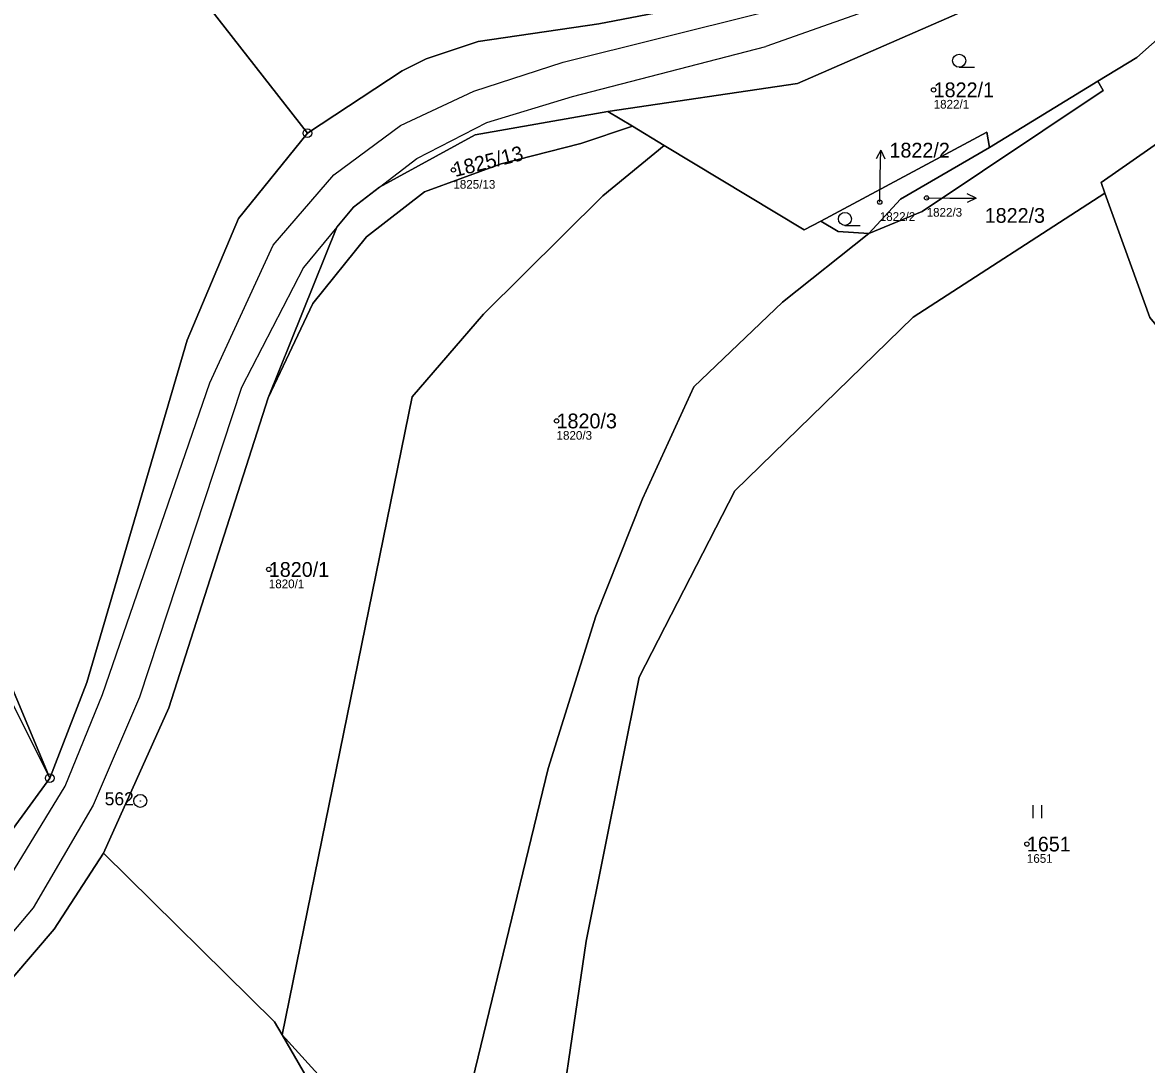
# Model space of a CAD drawing. Extents: x -762274 to -759271, y -1061928 to -1059060.
# Drawn here: x -761021.1 to -760891.6, y -1060368.9 to -1060248.8 of the extents above; entities that cross this region are included whole.
import ezdxf

# ---------------------------------------------------------------- set-up
doc = ezdxf.new("R2010")
doc.units = 0
for name, color, linetype in [('Definiční body', 7, 'Continuous'), ('Hranice parcel', 7, 'Continuous'), ('Parcelní čísla', 7, 'Continuous'), ('Polygon parcely', 7, 'Continuous'), ('Pop  PČ popisy', 7, 'Continuous'), ('Vnitřní kresba', 7, 'Continuous'), ('Značky bodu BP', 7, 'Continuous'), ('Značky kultur', 7, 'Continuous')]:
    doc.layers.add(name, color=color, linetype=linetype)

msp = doc.modelspace()

# ---------------------------------------------------------------- linework, layer by layer
at = {"layer": 'Definiční body'}
for centre in [(-760916.13, -1060256.56), (-760971.48, -1060265.79), (-760922.34, -1060269.5), (-760916.94, -1060269.01), (-760959.59, -1060294.71), (-760992.75, -1060311.82), (-760905.39, -1060343.46)]:
    msp.add_circle(centre, 0.25, dxfattribs=at)
at = {"layer": 'Hranice parcel'}
for p, q in [((-760909.68, -1060263.19), (-760897.21, -1060255.57)), ((-760953.67, -1060259.06), (-760950.85, -1060260.75)), ((-760950.85, -1060260.75), (-760947.17, -1060262.97)), ((-760974.43, -1060394.46), (-760991.21, -1060365.45))]:
    msp.add_line(p, q, dxfattribs=at)
for points in [[(-761078.48, -1060213.62), (-761057.56, -1060250.11), (-761042.29, -1060277.77), (-761018, -1060335.87)], [(-760988.31, -1060261.56), (-760977.4, -1060254.36), (-760974.6, -1060253), (-760968.64, -1060250.99), (-760954.7, -1060248.96), (-760947.29, -1060247.52), (-760940.52, -1060246.19), (-760931.32, -1060243.79), (-760922.41, -1060240.54), (-760918.23, -1060238.58), (-760916.79, -1060234.33)], [(-761006.62, -1060234.74), (-761002.03, -1060243.92), (-760988.31, -1060261.56)], [(-760897.21, -1060255.57), (-760892.72, -1060252.83), (-760874.41, -1060236.6)], [(-760904.18, -1060243.78), (-760912.52, -1060247.42), (-760931.82, -1060255.83), (-760953.67, -1060259.06)], [(-760874.93, -1060249.88), (-760883.71, -1060258.09), (-760896.84, -1060267.23), (-760896.39, -1060268.47)], [(-761018, -1060335.87), (-761037.77, -1060296.38), (-761044.15, -1060282.19), (-761061.78, -1060253.34)], [(-760897.21, -1060255.57), (-760896.58, -1060256.63), (-760917.46, -1060270.59), (-760923.61, -1060273.11)], [(-760992.81, -1060292.05), (-760984.91, -1060272.38), (-760983, -1060270.07), (-760980, -1060267.77), (-760968.98, -1060261.75), (-760953.67, -1060259.06)], [(-760988.31, -1060261.56), (-760996.24, -1060271.37), (-761002.17, -1060285.41), (-761013.73, -1060324.84), (-761018, -1060335.87)], [(-760950.85, -1060260.75), (-760956.8, -1060262.74), (-760965.96, -1060265.09), (-760974.8, -1060268.32), (-760981.51, -1060273.48), (-760987.67, -1060281.19), (-760992.81, -1060292.05)], [(-760929.15, -1060271.68), (-760909.99, -1060261.44), (-760909.68, -1060263.19)], [(-760991.21, -1060365.45), (-760976.24, -1060291.93), (-760967.99, -1060282.4), (-760954.26, -1060268.77), (-760947.17, -1060262.97)], [(-760947.17, -1060262.97), (-760931.05, -1060272.69), (-760929.15, -1060271.68)], [(-760923.61, -1060273.11), (-760919.95, -1060269.16), (-760909.68, -1060263.19)], [(-760896.39, -1060268.47), (-760918.5, -1060282.74), (-760939.03, -1060302.75), (-760950.07, -1060324.21), (-760956.19, -1060354.66), (-760960.46, -1060383.67)], [(-760886.39, -1060288.67), (-760891.22, -1060282.78), (-760896.39, -1060268.47)], [(-760929.15, -1060271.68), (-760927.14, -1060272.89), (-760923.61, -1060273.11)], [(-760923.61, -1060273.11), (-760933.56, -1060281.02), (-760943.77, -1060290.78), (-760949.7, -1060303.69), (-760955.07, -1060317.2), (-760960.55, -1060334.74), (-760970.58, -1060376.02), (-760972.56, -1060386.36)], [(-761011.8, -1060344.49), (-761004.26, -1060327.78), (-760992.81, -1060292.05)], [(-761046.15, -1060368.25), (-761043.61, -1060366.2), (-761038.65, -1060361.43), (-761033.71, -1060356.07), (-761024.82, -1060345.2), (-761018, -1060335.87)], [(-761011.8, -1060344.49), (-761017.49, -1060353.26), (-761031.8, -1060369.97), (-761043.24, -1060380.01), (-761063.63, -1060394.39)], [(-760991.21, -1060365.45), (-760992.08, -1060363.94), (-761011.8, -1060344.49)], [(-760972.56, -1060386.36), (-760978.82, -1060379.11), (-760991.21, -1060365.45)]]:
    msp.add_lwpolyline(points, dxfattribs=at)
at = {"layer": 'Polygon parcely'}
for points in [[(-760808.18, -1060131.44), (-760857.3, -1060213.18), (-760864.46, -1060224.27), (-760871.02, -1060232.35), (-760874.41, -1060236.6), (-760892.72, -1060252.83), (-760897.21, -1060255.57), (-760896.58, -1060256.63), (-760917.46, -1060270.59), (-760923.61, -1060273.11), (-760933.56, -1060281.02), (-760943.77, -1060290.78), (-760949.7, -1060303.69), (-760955.07, -1060317.2), (-760960.55, -1060334.74), (-760970.58, -1060376.02)], [(-760960.46, -1060383.67), (-760956.19, -1060354.66), (-760950.07, -1060324.21), (-760939.03, -1060302.75), (-760918.5, -1060282.74), (-760896.39, -1060268.47), (-760896.84, -1060267.23), (-760883.71, -1060258.09), (-760874.93, -1060249.88), (-760866.8, -1060242.22), (-760854.92, -1060227.15), (-760851.52, -1060222.69), (-760832.08, -1060190.27), (-760824.05, -1060177.19), (-760813.37, -1060159.25), (-760799.61, -1060136.58), (-760796.94, -1060132.77)], [(-761031.8, -1060369.97), (-761017.49, -1060353.26), (-761011.8, -1060344.49), (-761004.26, -1060327.78), (-760992.81, -1060292.05), (-760984.91, -1060272.38), (-760983, -1060270.07), (-760980, -1060267.77), (-760968.98, -1060261.75), (-760953.67, -1060259.06), (-760931.82, -1060255.83), (-760912.52, -1060247.42)], [(-760947.29, -1060247.52), (-760954.7, -1060248.96), (-760968.64, -1060250.99), (-760974.6, -1060253), (-760977.4, -1060254.36), (-760988.31, -1060261.56), (-760996.24, -1060271.37), (-761002.17, -1060285.41), (-761013.73, -1060324.84), (-761018, -1060335.87), (-761024.82, -1060345.2)]]:
    msp.add_lwpolyline(points, dxfattribs=at)
for points in [[(-761042.29, -1060277.77), (-761018, -1060335.87), (-761013.73, -1060324.84), (-761002.17, -1060285.41), (-760996.24, -1060271.37), (-760988.31, -1060261.56), (-761002.03, -1060243.92), (-761006.62, -1060234.74), (-761025.7, -1060196.58), (-761035.73, -1060193.93), (-761044.44, -1060195.02), (-761059.76, -1060201.51), (-761078.48, -1060213.62), (-761057.56, -1060250.11)], [(-761061.78, -1060253.34), (-761044.15, -1060282.19), (-761037.77, -1060296.38), (-761018, -1060335.87), (-761042.29, -1060277.77), (-761057.56, -1060250.11), (-761078.48, -1060213.62), (-761085.62, -1060218.24)], [(-760988.31, -1060261.56), (-760977.4, -1060254.36), (-760974.6, -1060253), (-760968.64, -1060250.99), (-760954.7, -1060248.96), (-760947.29, -1060247.52), (-760940.52, -1060246.19), (-760931.32, -1060243.79), (-760922.41, -1060240.54), (-760918.23, -1060238.58), (-760916.79, -1060234.33), (-760915.34, -1060230.03), (-760917.77, -1060228.61), (-760919.86, -1060227.54), (-760941.83, -1060216.26), (-761006.62, -1060234.74), (-761002.03, -1060243.92)], [(-760909.68, -1060263.19), (-760897.21, -1060255.57), (-760892.72, -1060252.83), (-760874.41, -1060236.6), (-760885.67, -1060239.75), (-760894.1, -1060241.59), (-760899.19, -1060241.61), (-760904.18, -1060243.78), (-760912.52, -1060247.42), (-760931.82, -1060255.83), (-760953.67, -1060259.06), (-760950.85, -1060260.75), (-760947.17, -1060262.97), (-760931.05, -1060272.69), (-760929.15, -1060271.68), (-760909.99, -1060261.44)], [(-760896.84, -1060267.23), (-760896.39, -1060268.47), (-760891.22, -1060282.78), (-760886.39, -1060288.67), (-760862.91, -1060264.89), (-760874.93, -1060249.88), (-760883.71, -1060258.09)], [(-761037.77, -1060296.38), (-761044.15, -1060282.19), (-761061.78, -1060253.34), (-761062.18, -1060253.64), (-761079.54, -1060266.53), (-761096.25, -1060279.05), (-761089.01, -1060288.61), (-761073.14, -1060315.12), (-761046.15, -1060368.25), (-761043.61, -1060366.2), (-761038.65, -1060361.43), (-761033.71, -1060356.07), (-761024.82, -1060345.2), (-761018, -1060335.87)], [(-760897.21, -1060255.57), (-760909.68, -1060263.19), (-760919.95, -1060269.16), (-760923.61, -1060273.11), (-760917.46, -1060270.59), (-760896.58, -1060256.63)], [(-760950.85, -1060260.75), (-760953.67, -1060259.06), (-760968.98, -1060261.75), (-760980, -1060267.77), (-760983, -1060270.07), (-760984.91, -1060272.38), (-760992.81, -1060292.05), (-760987.67, -1060281.19), (-760981.51, -1060273.48), (-760974.8, -1060268.32), (-760965.96, -1060265.09), (-760956.8, -1060262.74)], [(-760950.85, -1060260.75), (-760956.8, -1060262.74), (-760965.96, -1060265.09), (-760974.8, -1060268.32), (-760981.51, -1060273.48), (-760987.67, -1060281.19), (-760992.81, -1060292.05), (-761004.26, -1060327.78), (-761011.8, -1060344.49), (-760992.08, -1060363.94), (-760991.21, -1060365.45), (-760976.24, -1060291.93), (-760967.99, -1060282.4), (-760954.26, -1060268.77), (-760947.17, -1060262.97)], [(-760923.61, -1060273.11), (-760919.95, -1060269.16), (-760909.68, -1060263.19), (-760909.99, -1060261.44), (-760929.15, -1060271.68), (-760927.14, -1060272.89)], [(-760929.15, -1060271.68), (-760931.05, -1060272.69), (-760947.17, -1060262.97), (-760954.26, -1060268.77), (-760967.99, -1060282.4), (-760976.24, -1060291.93), (-760991.21, -1060365.45), (-760978.82, -1060379.11), (-760972.56, -1060386.36), (-760970.58, -1060376.02), (-760960.55, -1060334.74), (-760955.07, -1060317.2), (-760949.7, -1060303.69), (-760943.77, -1060290.78), (-760933.56, -1060281.02), (-760923.61, -1060273.11), (-760927.14, -1060272.89)], [(-760864.51, -1060358.38), (-760845.75, -1060340.74), (-760888.05, -1060290.93), (-760886.39, -1060288.67), (-760891.22, -1060282.78), (-760896.39, -1060268.47), (-760918.5, -1060282.74), (-760939.03, -1060302.75), (-760950.07, -1060324.21), (-760956.19, -1060354.66), (-760960.46, -1060383.67), (-760959.97, -1060389.32), (-760927.4, -1060424.04), (-760919.52, -1060414.57), (-760902.71, -1060395.38), (-760883.41, -1060376.1)], [(-761017.49, -1060353.26), (-761031.8, -1060369.97), (-761043.24, -1060380.01), (-761063.63, -1060394.39), (-761021.62, -1060461.75), (-760986.1, -1060427.01), (-760977.79, -1060413.47), (-760974.43, -1060394.46), (-760991.21, -1060365.45), (-760992.08, -1060363.94), (-761011.8, -1060344.49)], [(-760972.56, -1060386.36), (-760978.82, -1060379.11), (-760991.21, -1060365.45), (-760974.43, -1060394.46), (-760972.99, -1060388.6)]]:
    msp.add_lwpolyline(points, close=True, dxfattribs=at)
at = {"layer": 'Pop  PČ popisy'}
for p, q in [((-760922.23, -1060263.51), (-760922.75, -1060264.5)), ((-760922.28, -1060266.51), (-760922.23, -1060263.51)), ((-760922.23, -1060263.51), (-760921.74, -1060264.52)), ((-760922.34, -1060269.5), (-760922.28, -1060266.51)), ((-760916.94, -1060269.01), (-760914.25, -1060269.03)), ((-760914.25, -1060269.03), (-760911.25, -1060269.03)), ((-760911.25, -1060269.03), (-760912.25, -1060268.53)), ((-760911.25, -1060269.03), (-760912.25, -1060269.53))]:
    msp.add_line(p, q, dxfattribs=at)
at = {"layer": 'Vnitřní kresba'}
for p, q in [((-760919.57, -1060245.94), (-760935.47, -1060251.55)), ((-760958.83, -1060253.39), (-760936.16, -1060247.72)), ((-760957.74, -1060257.33), (-760935.47, -1060251.55)), ((-760969.11, -1060256.71), (-760958.83, -1060253.39)), ((-760977.57, -1060260.65), (-760969.11, -1060256.71)), ((-760967.61, -1060260.34), (-760957.74, -1060257.33)), ((-760975.69, -1060264.47), (-760967.61, -1060260.34)), ((-760985.24, -1060266.35), (-760977.57, -1060260.65)), ((-760980, -1060267.77), (-760975.69, -1060264.47)), ((-760992.26, -1060274.44), (-760985.24, -1060266.35)), ((-760984.91, -1060272.38), (-760988.76, -1060277.02)), ((-760999.56, -1060290.3), (-760992.26, -1060274.44)), ((-760988.76, -1060277.02), (-760995.9, -1060290.86)), ((-761011.92, -1060326.24), (-760999.56, -1060290.3)), ((-760995.9, -1060290.86), (-761007.64, -1060326.52)), ((-761016.21, -1060336.8), (-761011.92, -1060326.24)), ((-761007.64, -1060326.52), (-761012.98, -1060338.99)), ((-761022.92, -1060347.74), (-761016.21, -1060336.8)), ((-761012.98, -1060338.99), (-761019.92, -1060350.82)), ((-761019.92, -1060350.82), (-761033.64, -1060367.05))]:
    msp.add_line(p, q, dxfattribs=at)
at = {"layer": 'Značky bodu BP'}
for centre, radius in [((-760988.31, -1060261.56), 0.5), ((-760988.31, -1060261.56), 0.0303), ((-761018, -1060335.87), 0.5), ((-761018, -1060335.87), 0.0303), ((-761007.56, -1060338.49), 0.75), ((-761007.56, -1060338.49), 0.03)]:
    msp.add_circle(centre, radius, dxfattribs=at)
at = {"layer": 'Značky kultur'}
for p, q in [((-760913.19, -1060253.95), (-760911.44, -1060253.95)), ((-760926.35, -1060272.18), (-760924.6, -1060272.18)), ((-760904.67, -1060340.49), (-760904.67, -1060338.99)), ((-760903.67, -1060340.49), (-760903.67, -1060338.99))]:
    msp.add_line(p, q, dxfattribs=at)
for centre in [(-760913.19, -1060253.2), (-760926.35, -1060271.43)]:
    msp.add_circle(centre, 0.75, dxfattribs=at)

# ---------------------------------------------------------------- texts
at = {"layer": 'Definiční body'}
for s, p in [('1822/1', (-760916.13, -1060258.72)), ('1825/13', (-760971.48, -1060267.95)), ('1822/2', (-760922.34, -1060271.66)), ('1822/3', (-760916.94, -1060271.17)), ('1820/3', (-760959.59, -1060296.87)), ('1820/1', (-760992.75, -1060313.98)), ('1651', (-760905.39, -1060345.62))]:
    msp.add_text(s, height=1, dxfattribs=at).set_placement(p)
at = {"layer": 'Parcelní čísla'}
for s, p in [('1822/1', (-760916.13, -1060257.41)), ('1822/2', (-760921.22, -1060264.36)), ('1822/3', (-760910.25, -1060271.88)), ('1820/3', (-760959.59, -1060295.56)), ('1820/1', (-760992.75, -1060312.67)), ('1651', (-760905.39, -1060344.31))]:
    msp.add_text(s, height=1.7, dxfattribs=at).set_placement(p)
msp.add_text('1825/13', height=1.7, rotation=14, dxfattribs=at).set_placement((-760971.27, -1060266.61))
at = {"layer": 'Značky bodu BP'}
msp.add_text('562', height=1.5, dxfattribs=at).set_placement((-761011.66, -1060338.99))

doc.saveas('drawing.dxf')
